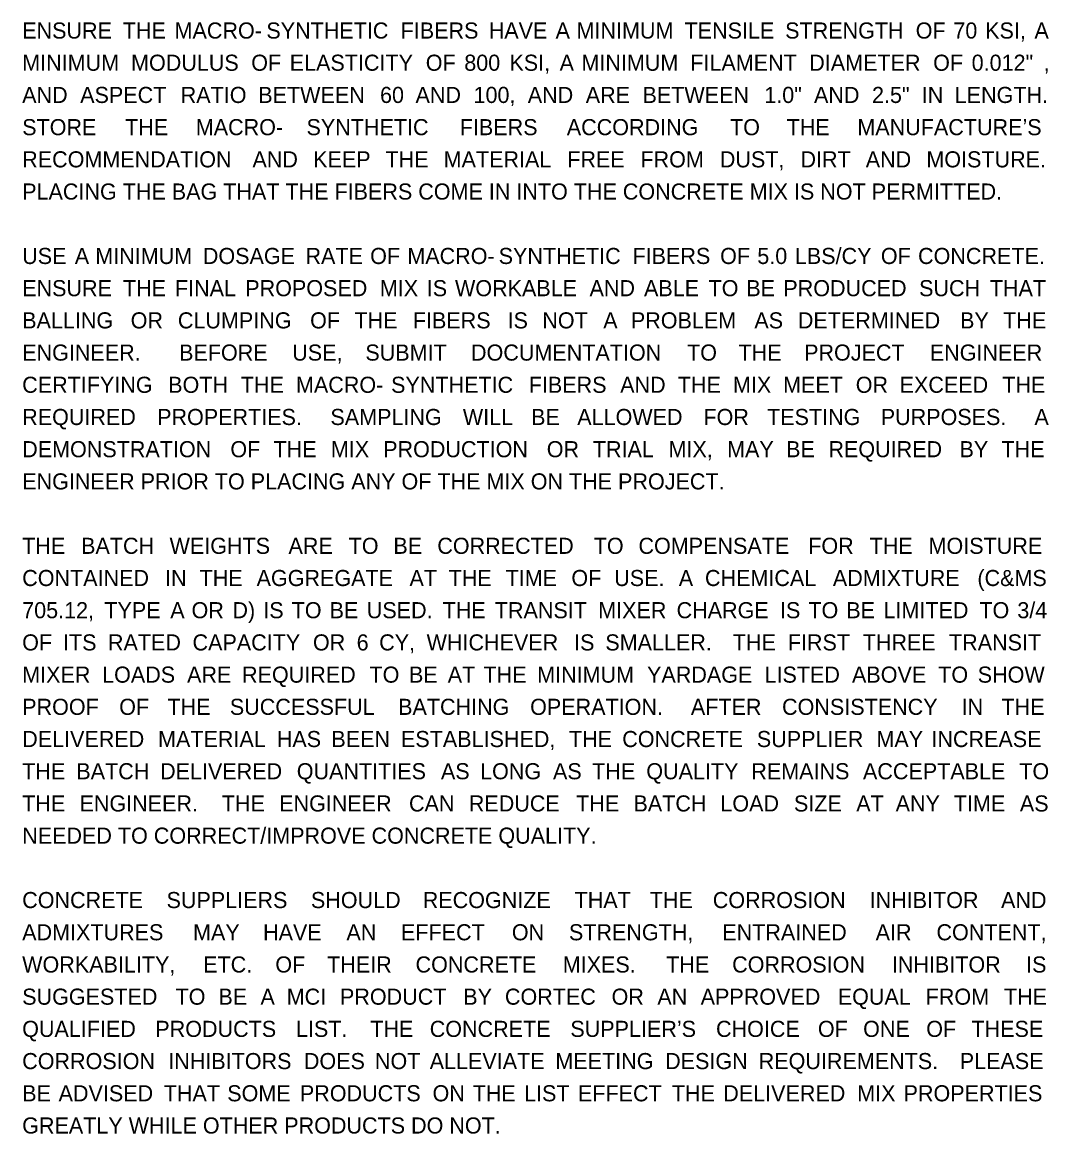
# Model space of a CAD drawing. Extents: x -20.1 to 34, y 0 to 22.
# Drawn here: x -20.11 to -11.18, y 1.68 to 11.34 of the extents above; entities that cross this region are included whole.
import ezdxf

# ---------------------------------------------------------------- set-up
doc = ezdxf.new("R2010")
doc.units = 0
doc.layers.add('SH_Text', color=7, linetype='Continuous')

msp = doc.modelspace()

# ---------------------------------------------------------------- texts
at = {"layer": 'SH_Text'}
for s, p in [('ENSURE ', (-20.1054, 11.2)), ('THE ', (-19.231, 11.2)), ('MACRO-', (-18.7807, 11.2)), ('SYNTHETIC ', (-17.9828, 11.2)), ('FIBERS ', (-16.8151, 11.2)), ('HAVE ', (-16.0495, 11.2)), ('A ', (-15.4685, 11.2)), ('MINIMUM ', (-15.2862, 11.2)), ('TENSILE ', (-14.3472, 11.2)), ('STRENGTH ', (-13.4728, 11.2)), ('OF ', (-12.3378, 11.2)), ('70 ', (-12.0106, 11.2)), ('KSI, ', (-11.7342, 11.2)), ('A ', (-11.3055, 11.2)), ('MINIMUM ', (-20.1054, 10.92)), ('MODULUS ', (-19.1589, 10.92)), ('OF ', (-18.1142, 10.92)), ('ELASTICITY ', (-17.7796, 10.92)), ('OF ', (-16.5969, 10.92)), ('800 ', (-16.2623, 10.92)), ('KSI, ', (-15.8696, 10.92)), ('A ', (-15.4335, 10.92)), ('MINIMUM ', (-15.2437, 10.92)), ('FILAMENT ', (-14.2972, 10.92)), ('DIAMETER ', (-13.2634, 10.92)), ('OF ', (-12.1861, 10.92)), ('0.012" ', (-11.8514, 10.92)), (', ', (-11.2262, 10.92)), ('AND ', (-20.1054, 10.64)), ('ASPECT ', (-19.6012, 10.64)), ('RATIO ', (-18.7274, 10.64)), ('BETWEEN ', (-18.053, 10.64)), ('60 ', (-16.9945, 10.64)), ('AND ', (-16.686, 10.64)), ('100, ', (-16.1818, 10.64)), ('AND ', (-15.7102, 10.64)), ('ARE ', (-15.2061, 10.64)), ('BETWEEN ', (-14.7127, 10.64)), ('1.0" ', (-13.6542, 10.64)), ('AND ', (-13.2219, 10.64)), ('2.5" ', (-12.7177, 10.64)), ('IN ', (-12.2854, 10.64)), ('LENGTH.  ', (-11.9987, 10.64)), ('STORE ', (-20.1054, 10.36)), ('THE ', (-19.2113, 10.36)), ('MACRO-', (-18.5963, 10.36)), ('SYNTHETIC ', (-17.6337, 10.36)), ('FIBERS ', (-16.3013, 10.36)), ('ACCORDING ', (-15.371, 10.36)), ('TO ', (-13.9518, 10.36)), ('THE ', (-13.46, 10.36)), ('MANUFACTURE’S ', (-12.845, 10.36)), ('RECOMMENDATION ', (-20.1054, 10.08)), ('AND ', (-18.1036, 10.08)), ('KEEP ', (-17.5763, 10.08)), ('THE ', (-16.9472, 10.08)), ('MATERIAL ', (-16.4416, 10.08)), ('FREE ', (-15.367, 10.08)), ('FROM ', (-14.7309, 10.08)), ('DUST, ', (-14.0407, 10.08)), ('DIRT ', (-13.3395, 10.08)), ('AND ', (-12.7723, 10.08)), ('MOISTURE.  ', (-12.245, 10.08)), ('PLACING THE BAG THAT THE FIBERS COME IN INTO THE CONCRETE MIX IS NOT PERMITTED.', (-20.1054, 9.8)), ('USE ', (-20.1054, 9.24)), ('A ', (-19.6481, 9.24)), ('MINIMUM ', (-19.4698, 9.24)), ('DOSAGE ', (-18.5348, 9.24)), ('RATE ', (-17.6427, 9.24)), ('OF ', (-17.0804, 9.24)), ('MACRO-', (-16.7572, 9.24)), ('SYNTHETIC ', (-15.9633, 9.24)), ('FIBERS ', (-14.7996, 9.24)), ('OF ', (-14.038, 9.24)), ('5.0 ', (-13.7148, 9.24)), ('LBS/CY ', (-13.388, 9.24)), ('OF ', (-12.6407, 9.24)), ('CONCRETE.  ', (-12.3175, 9.24)), ('ENSURE ', (-20.1054, 8.96)), ('THE ', (-19.2294, 8.96)), ('FINAL ', (-18.7775, 8.96)), ('PROPOSED ', (-18.1661, 8.96)), ('MIX ', (-16.9965, 8.96)), ('IS ', (-16.5882, 8.96)), ('WORKABLE ', (-16.3427, 8.96)), ('AND ', (-15.1733, 8.96)), ('ABLE ', (-14.6996, 8.96)), ('TO ', (-14.1387, 8.96)), ('BE ', (-13.81, 8.96)), ('PRODUCED ', (-13.4883, 8.96)), ('SUCH ', (-12.3082, 8.96)), ('THAT ', (-11.6932, 8.96)), ('BALLING ', (-20.1054, 8.68)), ('OR ', (-19.1622, 8.68)), ('CLUMPING ', (-18.7519, 8.68)), ('OF ', (-17.6025, 8.68)), ('THE ', (-17.2174, 8.68)), ('FIBERS ', (-16.7092, 8.68)), ('IS ', (-15.8857, 8.68)), ('NOT ', (-15.5839, 8.68)), ('A ', (-15.0541, 8.68)), ('PROBLEM ', (-14.8139, 8.68)), ('AS ', (-13.7404, 8.68)), ('DETERMINED ', (-13.3624, 8.68)), ('BY ', (-11.9521, 8.68)), ('THE ', (-11.5777, 8.68)), ('ENGINEER.   ', (-20.1054, 8.4)), ('BEFORE ', (-18.7414, 8.4)), ('USE, ', (-17.7578, 8.4)), ('SUBMIT ', (-17.122, 8.4)), ('DOCUMENTATION ', (-16.2037, 8.4)), ('TO ', (-14.3255, 8.4)), ('THE ', (-13.8782, 8.4)), ('PROJECT ', (-13.3077, 8.4)), ('ENGINEER ', (-12.2154, 8.4)), ('CERTIFYING ', (-20.1054, 8.12)), ('BOTH ', (-18.8362, 8.12)), ('THE ', (-18.2047, 8.12)), ('MACRO-', (-17.7253, 8.12)), ('SYNTHETIC ', (-16.8983, 8.12)), ('FIBERS ', (-15.7016, 8.12)), ('AND ', (-14.9069, 8.12)), ('THE ', (-14.4058, 8.12)), ('MIX ', (-13.9264, 8.12)), ('MEET ', (-13.4906, 8.12)), ('OR ', (-12.8591, 8.12)), ('EXCEED ', (-12.4776, 8.12)), ('THE ', (-11.585, 8.12)), ('REQUIRED ', (-20.1054, 7.84)), ('PROPERTIES.  ', (-18.9324, 7.84)), ('SAMPLING ', (-17.4259, 7.84)), ('WILL ', (-16.2746, 7.84)), ('BE ', (-15.6814, 7.84)), ('ALLOWED ', (-15.2801, 7.84)), ('FOR ', (-14.1832, 7.84)), ('TESTING ', (-13.6299, 7.84)), ('PURPOSES.  ', (-12.6417, 7.84)), ('A ', (-11.3055, 7.84)), ('DEMONSTRATION ', (-20.1054, 7.56)), ('OF ', (-18.2956, 7.56)), ('THE ', (-17.9204, 7.56)), ('MIX ', (-17.422, 7.56)), ('PRODUCTION ', (-16.9672, 7.56)), ('OR ', (-15.5451, 7.56)), ('TRIAL ', (-15.1445, 7.56)), ('MIX, ', (-14.4867, 7.56)), ('MAY ', (-13.9775, 7.56)), ('BE ', (-13.4645, 7.56)), ('REQUIRED ', (-13.0965, 7.56)), ('BY ', (-11.9568, 7.56)), ('THE ', (-11.5922, 7.56)), ('ENGINEER PRIOR TO PLACING ANY OF THE MIX ON THE PROJECT.  ', (-20.1054, 7.28)), ('BATCH ', (-19.5933, 6.72)), ('WEIGHTS ', (-18.824, 6.72)), ('TO ', (-17.2673, 6.72)), ('CORRECTED ', (-16.4967, 6.72)), ('TO ', (-15.1368, 6.72)), ('COMPENSATE ', (-14.7479, 6.72)), ('FOR ', (-13.272, 6.72)), ('MOISTURE ', (-12.2262, 6.72)), ('THE ', (-20.1054, 6.72)), ('ARE ', (-17.7904, 6.72)), ('BE ', (-16.8784, 6.72)), ('THE ', (-12.7382, 6.72)), ('CONTAINED ', (-20.1054, 6.44)), ('IN ', (-18.8634, 6.44)), ('THE ', (-18.5633, 6.44)), ('AGGREGATE ', (-18.0676, 6.44)), ('AT ', (-16.7384, 6.44)), ('THE ', (-16.3985, 6.44)), ('TIME ', (-15.9028, 6.44)), ('OF ', (-15.3311, 6.44)), ('USE. ', (-14.9585, 6.44)), ('A ', (-14.3975, 6.44)), ('CHEMICAL ', (-14.1698, 6.44)), ('ADMIXTURE ', (-13.058, 6.44)), ('(C&MS ', (-11.8015, 6.44)), ('705.12, ', (-20.1054, 6.16)), ('TYPE ', (-19.3912, 6.16)), ('A ', (-18.8182, 6.16)), ('OR ', (-18.6331, 6.16)), ('D) ', (-18.2777, 6.16)), ('IS ', (-18.0095, 6.16)), ('TO ', (-17.7627, 6.16)), ('BE ', (-17.4327, 6.16)), ('USED. ', (-17.1097, 6.16)), ('THE ', (-16.45, 6.16)), ('TRANSIT ', (-15.9967, 6.16)), ('MIXER ', (-15.0979, 6.16)), ('CHARGE ', (-14.4165, 6.16)), ('IS ', (-13.5176, 6.16)), ('TO ', (-13.2708, 6.16)), ('BE ', (-12.9408, 6.16)), ('LIMITED ', (-12.6178, 6.16)), ('TO ', (-11.7843, 6.16)), ('3/4 ', (-11.4543, 6.16)), ('OF ', (-20.1054, 5.88)), ('ITS ', (-19.7506, 5.88)), ('RATED ', (-19.3597, 5.88)), ('CAPACITY ', (-18.6246, 5.88)), ('OR ', (-17.5776, 5.88)), ('6 ', (-17.1976, 5.88)), ('CY, ', (-17.0022, 5.88)), ('WHICHEVER ', (-16.5896, 5.88)), ('IS ', (-15.3074, 5.88)), ('SMALLER.  ', (-15.036, 5.88)), ('THE ', (-13.9276, 5.88)), ('FIRST ', (-13.4497, 5.88)), ('THREE ', (-12.798, 5.88)), ('TRANSIT ', (-12.0483, 5.88)), ('MIXER ', (-20.1054, 5.6)), ('LOADS ', (-19.4105, 5.6)), ('ARE ', (-18.6719, 5.6)), ('REQUIRED ', (-18.1942, 5.6)), ('TO ', (-17.0862, 5.6)), ('BE ', (-16.7426, 5.6)), ('AT ', (-16.4062, 5.6)), ('THE ', (-16.0953, 5.6)), ('MINIMUM ', (-15.6286, 5.6)), ('YARDAGE ', (-14.6732, 5.6)), ('LISTED ', (-13.6519, 5.6)), ('ABOVE ', (-12.8916, 5.6)), ('TO ', (-12.1421, 5.6)), ('SHOW ', (-11.7985, 5.6)), ('PROOF ', (-20.1054, 5.32)), ('OF ', (-19.2621, 5.32)), ('THE ', (-18.8428, 5.32)), ('SUCCESSFUL ', (-18.3003, 5.32)), ('BATCHING ', (-16.8373, 5.32)), ('OPERATION.  ', (-15.6898, 5.32)), ('AFTER ', (-14.2923, 5.32)), ('CONSISTENCY ', (-13.4998, 5.32)), ('IN ', (-11.939, 5.32)), ('THE ', (-11.5922, 5.32)), ('DELIVERED ', (-20.1054, 5.04)), ('MATERIAL ', (-18.9243, 5.04)), ('HAS ', (-17.8919, 5.04)), ('BEEN ', (-17.4175, 5.04)), ('ESTABLISHED, ', (-16.8125, 5.04)), ('THE ', (-15.3524, 5.04)), ('CONCRETE ', (-14.8889, 5.04)), ('SUPPLIER ', (-13.719, 5.04)), ('MAY ', (-12.6792, 5.04)), ('INCREASE ', (-12.2011, 5.04)), ('THE ', (-20.1054, 4.76)), ('BATCH ', (-19.6347, 4.76)), ('DELIVERED ', (-18.9067, 4.76)), ('QUANTITIES ', (-17.7184, 4.76)), ('AS ', (-16.4651, 4.76)), ('LONG ', (-16.1247, 4.76)), ('AS ', (-15.4909, 4.76)), ('THE ', (-15.1505, 4.76)), ('QUALITY ', (-14.6798, 4.76)), ('REMAINS ', (-13.7669, 4.76)), ('ACCEPTABLE ', (-12.7961, 4.76)), ('TO ', (-11.4374, 4.76)), ('THE ', (-20.1054, 4.48)), ('ENGINEER.  ', (-19.6072, 4.48)), ('THE ', (-18.3698, 4.48)), ('ENGINEER ', (-17.8715, 4.48)), ('CAN ', (-16.7428, 4.48)), ('REDUCE ', (-16.2227, 4.48)), ('THE ', (-15.2897, 4.48)), ('BATCH ', (-14.7914, 4.48)), ('LOAD ', (-14.0359, 4.48)), ('SIZE ', (-13.3963, 4.48)), ('AT ', (-12.8545, 4.48)), ('ANY ', (-12.5121, 4.48)), ('TIME ', (-12.0064, 4.48)), ('AS ', (-11.4322, 4.48)), ('NEEDED TO CORRECT/IMPROVE CONCRETE QUALITY.', (-20.1054, 4.2)), ('CONCRETE ', (-20.1054, 3.64)), ('SUPPLIERS ', (-18.8506, 3.64)), ('SHOULD ', (-17.5955, 3.64)), ('RECOGNIZE ', (-16.6233, 3.64)), ('THAT ', (-15.3033, 3.64)), ('THE ', (-14.65, 3.64)), ('CORROSION ', (-14.1017, 3.64)), ('INHIBITOR ', (-12.7383, 3.64)), ('AND ', (-11.5959, 3.64)), ('ADMIXTURES ', (-20.1054, 3.36)), ('MAY ', (-18.62, 3.36)), ('HAVE ', (-18.0114, 3.36)), ('AN ', (-17.2866, 3.36)), ('EFFECT ', (-16.8121, 3.36)), ('ON ', (-15.8486, 3.36)), ('STRENGTH, ', (-15.3524, 3.36)), ('ENTRAINED ', (-14.0193, 3.36)), ('AIR ', (-12.6861, 3.36)), ('CONTENT, ', (-12.1573, 3.36)), ('WORKABILITY, ', (-20.1054, 3.08)), ('ETC. ', (-18.5322, 3.08)), ('OF ', (-17.9047, 3.08)), ('THEIR ', (-17.4546, 3.08)), ('CONCRETE ', (-16.6858, 3.08)), ('MIXES.  ', (-15.406, 3.08)), ('THE ', (-14.5067, 3.08)), ('CORROSION ', (-13.9335, 3.08)), ('INHIBITOR ', (-12.5451, 3.08)), ('IS ', (-11.3778, 3.08)), ('SUGGESTED ', (-20.1054, 2.8)), ('TO ', (-18.7723, 2.8)), ('BE ', (-18.3996, 2.8)), ('A ', (-18.0339, 2.8)), ('MCI ', (-17.806, 2.8)), ('PRODUCT ', (-17.3429, 2.8)), ('BY ', (-16.2709, 2.8)), ('CORTEC ', (-15.9088, 2.8)), ('OR ', (-14.9817, 2.8)), ('AN ', (-14.5836, 2.8)), ('APPROVED ', (-14.2072, 2.8)), ('EQUAL ', (-13.0153, 2.8)), ('FROM ', (-12.251, 2.8)), ('THE ', (-11.5705, 2.8)), ('QUALIFIED ', (-20.1054, 2.52)), ('PRODUCTS ', (-18.948, 2.52)), ('LIST.  ', (-17.7253, 2.52)), ('THE ', (-17.0788, 2.52)), ('CONCRETE ', (-16.5627, 2.52)), ('SUPPLIER’S ', (-15.34, 2.52)), ('CHOICE ', (-14.0736, 2.52)), ('OF ', (-13.188, 2.52)), ('ONE ', (-12.795, 2.52)), ('OF ', (-12.2462, 2.52)), ('THESE ', (-11.8532, 2.52)), ('CORROSION ', (-20.1054, 2.24)), ('INHIBITORS ', (-18.8358, 2.24)), ('DOES ', (-17.6567, 2.24)), ('NOT ', (-17.039, 2.24)), ('ALLEVIATE ', (-16.5629, 2.24)), ('MEETING ', (-15.4704, 2.24)), ('DESIGN ', (-14.516, 2.24)), ('REQUIREMENTS.  ', (-13.7028, 2.24)), ('PLEASE ', (-11.9549, 2.24)), ('BE ', (-20.1054, 1.96)), ('ADVISED ', (-19.7889, 1.96)), ('THAT ', (-18.8746, 1.96)), ('SOME ', (-18.3228, 1.96)), ('PRODUCTS ', (-17.6913, 1.96)), ('ON ', (-16.538, 1.96)), ('THE ', (-16.1891, 1.96)), ('LIST ', (-15.7424, 1.96)), ('EFFECT ', (-15.2738, 1.96)), ('THE ', (-14.4576, 1.96)), ('DELIVERED ', (-14.0108, 1.96)), ('MIX ', (-12.8464, 1.96)), ('PROPERTIES ', (-12.4432, 1.96)), ('GREATLY WHILE OTHER PRODUCTS DO NOT.', (-20.1054, 1.68))]:
    msp.add_text(s, height=0.14, dxfattribs=at).set_placement(p)

doc.saveas('drawing.dxf')
